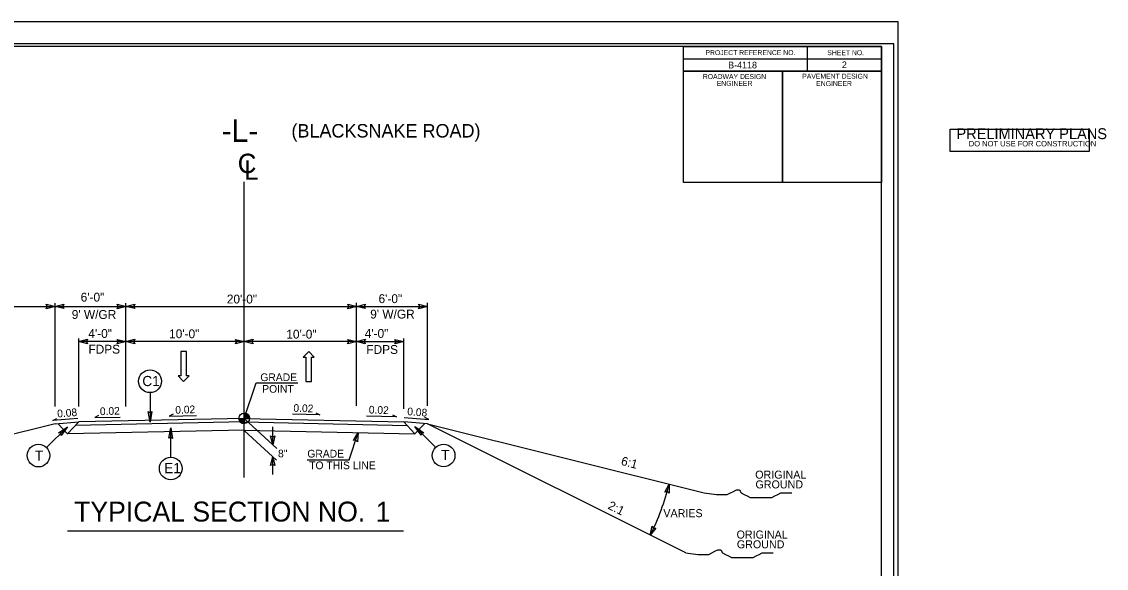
# Model space of a CAD drawing. Extents: x 573980 to 574178, y -53449 to -53334.
# Drawn here: x 574063.6 to 574178.2, y -53391.7 to -53334 of the extents above; entities that cross this region are included whole.
import ezdxf

# ---------------------------------------------------------------- set-up
doc = ezdxf.new("R2010")
doc.units = 0
for name, color, linetype in [('Old_Level_1', 7, 'Continuous'), ('Old_Level_11', 7, 'Continuous'), ('Old_Level_2', 7, 'Continuous'), ('Old_Level_3', 7, 'Continuous'), ('Prop Dimension Text', 7, 'Continuous'), ('Prop Lane Arrow CELL', 7, 'Continuous'), ('Sheet Data Field CELL', 7, 'Continuous'), ('Sheet Plot Border Inside CELL', 7, 'Continuous'), ('Sheet Plot Border Outside CELL', 7, 'Continuous'), ('Sheet Sticker Preliminary CELL', 7, 'Continuous'), ('Sheet Typical CELL', 7, 'Continuous'), ('Typical Berm CELL', 7, 'Continuous'), ('Typical Berm Information CELL', 7, 'Continuous'), ('Typical Grade Point Symbol CELL', 7, 'Continuous'), ('Typical ID Circle CELL', 7, 'Continuous'), ('Typical Pavement Slope CELL', 7, 'Continuous'), ('Typical Slope Point Local CELL', 7, 'Continuous'), ('Typical Terminator CELL', 7, 'Continuous'), ('Typical Text Centerline CELL', 7, 'Continuous'), ('Typical Text General CELL', 7, 'Continuous'), ('Typical Text Grade Point CELL', 7, 'Continuous'), ('Typical Text ID Circle CELL', 7, 'Continuous')]:
    doc.layers.add(name, color=color, linetype=linetype)

# ---------------------------------------------------------------- blocks, each defined once
blk = doc.blocks.new('TERMINATOR')
at = {"layer": 'Typical Terminator CELL'}
blk.add_lwpolyline([(-0.469, 0.081), (0, 0), (-0.471, -0.083), (-0.411, 0)], close=True, dxfattribs=at)
blk = doc.blocks.new('Lane Arrow Through')
at = {"layer": 'Prop Lane Arrow CELL'}
for p, q in [((-17.15, 1.6), (-3.15, 1.6)), ((-17.15, -1.7), (-17.15, 1.6)), ((-3.15, 1.6), (-3.15, 3.1)), ((-3.15, 3.1), (0, 0)), ((0, 0), (-3.15, -3.2)), ((-3.15, -1.7), (-17.15, -1.7)), ((-3.15, -3.2), (-3.15, -1.7))]:
    blk.add_line(p, q, dxfattribs=at)

msp = doc.modelspace()

# ---------------------------------------------------------------- linework, layer by layer
at = {"layer": 'Old_Level_1'}
msp.add_line((574068.4, -53387.77), (574103.91, -53387.77), dxfattribs=at)
at = {"layer": 'Old_Level_2'}
msp.add_line((574087.08, -53382.15), (574087.08, -53350.9), dxfattribs=at)
at = {"layer": 'Prop Dimension Text'}
for p, q in [((574057.08, -53364.07), (574106.45, -53364.07)), ((574067.08, -53374.65), (574067.08, -53363.72)), ((574074.58, -53374.65), (574074.58, -53363.72)), ((574098.95, -53374.59), (574098.95, -53363.69)), ((574106.45, -53374.59), (574106.45, -53363.69)), ((574069.58, -53374.65), (574069.58, -53367.47)), ((574074.58, -53367.78), (574069.58, -53367.78)), ((574099.02, -53367.78), (574072.08, -53367.78)), ((574098.95, -53374.59), (574098.95, -53367.4)), ((574098.95, -53367.78), (574103.95, -53367.78)), ((574103.95, -53374.88), (574103.95, -53367.47)), ((574087.14, -53375.97), (574090.52, -53379.08)), ((574090.09, -53378.69), (574090.09, -53376.79)), ((574087.12, -53377.21), (574090.49, -53380.33)), ((574090.09, -53381.83), (574090.09, -53379.96))]:
    msp.add_line(p, q, dxfattribs=at)
msp.add_arc((574106.45, -53376.46), 26.34, 333.4341, 345.9638, dxfattribs=at)
at = {"layer": 'Sheet Plot Border Inside CELL'}
msp.add_lwpolyline([(574155.75, -53336.33), (573981.44, -53336.33), (573981.44, -53446.69), (574155.75, -53446.69)], close=True, dxfattribs=at)
at = {"layer": 'Sheet Plot Border Outside CELL'}
msp.add_lwpolyline([(574156.22, -53333.98), (573980.08, -53333.98), (573980.08, -53449.04), (574156.22, -53449.04)], close=True, dxfattribs=at)
at = {"layer": 'Sheet Sticker Preliminary CELL'}
msp.add_lwpolyline([(574161.72, -53347.7), (574161.72, -53345.35), (574176.42, -53345.35), (574176.42, -53347.7)], close=True, dxfattribs=at)
at = {"layer": 'Sheet Typical CELL'}
for p, q in [((574146.6, -53336.6), (574146.6, -53339.22)), ((574133.52, -53337.91), (574154.44, -53337.91)), ((574143.98, -53339.22), (574143.98, -53350.98))]:
    msp.add_line(p, q, dxfattribs=at)
for points in [[(574154.44, -53336.6), (573997.55, -53336.6), (573997.55, -53446.42), (574154.44, -53446.42)], [(574133.52, -53336.6), (574154.44, -53336.6), (574154.44, -53339.22), (574133.52, -53339.22)], [(574133.52, -53339.22), (574143.98, -53339.22), (574143.98, -53350.98), (574133.52, -53350.98)], [(574143.98, -53339.22), (574154.44, -53339.22), (574154.44, -53350.98), (574143.98, -53350.98)]]:
    msp.add_lwpolyline(points, close=True, dxfattribs=at)
at = {"layer": 'Typical Berm CELL'}
for p, q in [((574087.08, -53375.9), (574069.58, -53376.27)), ((574087.08, -53375.9), (574103.95, -53376.26)), ((574068.39, -53377.55), (574067.37, -53376.45)), ((574068.39, -53377.55), (574069.58, -53376.27)), ((574087.1, -53377.15), (574068.39, -53377.55)), ((574087.08, -53376.28), (574069.22, -53376.65)), ((574087.05, -53377.15), (574105.13, -53377.53)), ((574087.07, -53376.28), (574104.3, -53376.64)), ((574105.13, -53377.53), (574103.95, -53376.26)), ((574105.13, -53377.53), (574106.16, -53376.43))]:
    msp.add_line(p, q, dxfattribs=at)
at = {"layer": 'Typical Berm Information CELL'}
for p, q in [((574071.69, -53375.61), (574071.28, -53375.82)), ((574071.28, -53375.82), (574073.96, -53375.76)), ((574079.58, -53375.45), (574079.16, -53375.66)), ((574079.16, -53375.66), (574082.02, -53375.6)), ((574095.07, -53375.53), (574092.19, -53375.47)), ((574094.66, -53375.32), (574095.07, -53375.53)), ((574103.18, -53375.74), (574100.01, -53375.67)), ((574102.76, -53375.53), (574103.18, -53375.74))]:
    msp.add_line(p, q, dxfattribs=at)
at = {"layer": 'Typical Grade Point Symbol CELL'}
for p, q in [((574087.08, -53375.9), (574088.33, -53372.15)), ((574086.52, -53375.9), (574087.08, -53375.9)), ((574087.08, -53375.9), (574087.08, -53375.34)), ((574087.64, -53375.9), (574087.08, -53375.9)), ((574087.08, -53376.46), (574087.08, -53375.9)), ((574087.08, -53375.9), (574087.08, -53376.46)), ((574098.17, -53380.29), (574099.13, -53377.41))]:
    msp.add_line(p, q, dxfattribs=at)
for points in [[(574086.52, -53375.9), (574086.52, -53375.96)], [(574086.53, -53375.9), (574086.53, -53376.03)], [(574086.54, -53375.9), (574086.54, -53376.07)], [(574086.55, -53375.9), (574086.55, -53376.1)], [(574086.56, -53375.9), (574086.56, -53376.13)], [(574086.58, -53375.9), (574086.58, -53376.15)], [(574086.59, -53375.9), (574086.59, -53376.17)], [(574086.6, -53375.9), (574086.6, -53376.19)], [(574086.61, -53375.9), (574086.61, -53376.21)], [(574086.62, -53375.9), (574086.62, -53376.23)], [(574086.63, -53375.9), (574086.63, -53376.24)], [(574086.64, -53375.9), (574086.64, -53376.26)], [(574086.65, -53375.9), (574086.65, -53376.27)], [(574086.67, -53375.9), (574086.67, -53376.28)], [(574086.68, -53375.9), (574086.68, -53376.3)], [(574086.69, -53375.9), (574086.69, -53376.31)], [(574086.7, -53375.9), (574086.7, -53376.32)], [(574086.71, -53375.9), (574086.71, -53376.33)], [(574086.72, -53375.9), (574086.72, -53376.34)], [(574086.73, -53375.9), (574086.73, -53376.35)], [(574086.74, -53375.9), (574086.74, -53376.35)], [(574086.75, -53375.9), (574086.75, -53376.36)], [(574086.77, -53375.9), (574086.77, -53376.37)], [(574086.78, -53375.9), (574086.78, -53376.38)], [(574086.79, -53375.9), (574086.79, -53376.38)], [(574086.8, -53375.9), (574086.8, -53376.39)], [(574086.81, -53375.9), (574086.81, -53376.4)], [(574086.82, -53375.9), (574086.82, -53376.4)], [(574086.83, -53375.9), (574086.83, -53376.41)], [(574086.84, -53375.9), (574086.84, -53376.41)], [(574086.86, -53375.9), (574086.86, -53376.42)], [(574086.87, -53375.9), (574086.87, -53376.42)], [(574086.88, -53375.9), (574086.88, -53376.43)], [(574086.89, -53375.9), (574086.89, -53376.43)], [(574086.9, -53375.9), (574086.9, -53376.43)], [(574086.91, -53375.9), (574086.91, -53376.44)], [(574086.92, -53375.9), (574086.92, -53376.44)], [(574086.93, -53375.9), (574086.93, -53376.44)], [(574086.95, -53375.9), (574086.95, -53376.45)], [(574086.96, -53375.9), (574086.96, -53376.45)], [(574086.97, -53375.9), (574086.97, -53376.45)], [(574086.98, -53375.9), (574086.98, -53376.45)], [(574086.99, -53375.9), (574086.99, -53376.46)], [(574087, -53375.9), (574087, -53376.46)], [(574087.01, -53375.9), (574087.01, -53376.46)], [(574087.02, -53375.9), (574087.02, -53376.46)], [(574087.03, -53375.9), (574087.03, -53376.46)], [(574087.05, -53375.9), (574087.05, -53376.46)], [(574087.06, -53375.9), (574087.06, -53376.46)], [(574087.07, -53375.9), (574087.07, -53376.46), (574087.07, -53376.46)], [(574087.08, -53375.34), (574087.08, -53375.34), (574087.08, -53375.9)], [(574087.09, -53375.34), (574087.09, -53375.9)], [(574087.1, -53375.35), (574087.1, -53375.9)], [(574087.12, -53375.35), (574087.12, -53375.9)], [(574087.13, -53375.35), (574087.13, -53375.9)], [(574087.14, -53375.35), (574087.14, -53375.9)], [(574087.15, -53375.35), (574087.15, -53375.9)], [(574087.16, -53375.35), (574087.16, -53375.9)], [(574087.17, -53375.35), (574087.17, -53375.9)], [(574087.18, -53375.35), (574087.18, -53375.9)], [(574087.19, -53375.36), (574087.19, -53375.9)], [(574087.2, -53375.36), (574087.2, -53375.9)], [(574087.22, -53375.36), (574087.22, -53375.9)], [(574087.23, -53375.37), (574087.23, -53375.9)], [(574087.24, -53375.37), (574087.24, -53375.9)], [(574087.25, -53375.37), (574087.25, -53375.9)], [(574087.26, -53375.38), (574087.26, -53375.9)], [(574087.27, -53375.38), (574087.27, -53375.9)], [(574087.28, -53375.38), (574087.28, -53375.9)], [(574087.29, -53375.39), (574087.29, -53375.9)], [(574087.31, -53375.39), (574087.31, -53375.9)], [(574087.32, -53375.4), (574087.32, -53375.9)], [(574087.33, -53375.4), (574087.33, -53375.9)], [(574087.34, -53375.41), (574087.34, -53375.9)], [(574087.35, -53375.42), (574087.35, -53375.9)], [(574087.36, -53375.42), (574087.36, -53375.9)], [(574087.37, -53375.43), (574087.37, -53375.9)], [(574087.38, -53375.44), (574087.38, -53375.9)], [(574087.4, -53375.44), (574087.4, -53375.9)], [(574087.41, -53375.45), (574087.41, -53375.9)], [(574087.42, -53375.46), (574087.42, -53375.9)], [(574087.43, -53375.47), (574087.43, -53375.9)], [(574087.44, -53375.48), (574087.44, -53375.9)], [(574087.45, -53375.49), (574087.45, -53375.9)], [(574087.46, -53375.5), (574087.46, -53375.9)], [(574087.47, -53375.51), (574087.47, -53375.9)], [(574087.48, -53375.52), (574087.48, -53375.9)], [(574087.5, -53375.53), (574087.5, -53375.9)], [(574087.51, -53375.55), (574087.51, -53375.9)], [(574087.52, -53375.56), (574087.52, -53375.9)], [(574087.53, -53375.58), (574087.53, -53375.9)], [(574087.54, -53375.59), (574087.54, -53375.9)], [(574087.55, -53375.61), (574087.55, -53375.9)], [(574087.56, -53375.63), (574087.56, -53375.9)], [(574087.57, -53375.65), (574087.57, -53375.9)], [(574087.59, -53375.67), (574087.59, -53375.9)], [(574087.6, -53375.7), (574087.6, -53375.9)], [(574087.61, -53375.73), (574087.61, -53375.9)], [(574087.62, -53375.77), (574087.62, -53375.9)], [(574087.63, -53375.82), (574087.63, -53375.9)]]:
    msp.add_lwpolyline(points, dxfattribs=at)
msp.add_circle((574087.08, -53375.9), 0.559, dxfattribs=at)
for start, end in [(179.9905, 269.9905), (359.9905, 89.9905)]:
    msp.add_arc((574087.08, -53375.9), 0.559, start, end, dxfattribs=at)
at = {"layer": 'Typical ID Circle CELL'}
for p, q in [((574077.12, -53373.18), (574077.12, -53376.29)), ((574066.18, -53378.98), (574068.38, -53376.79)), ((574079.31, -53380), (574079.31, -53376.89)), ((574107.32, -53378.97), (574105.12, -53376.77))]:
    msp.add_line(p, q, dxfattribs=at)
for centre in [(574077.12, -53371.98), (574065.33, -53379.83), (574108.16, -53379.82), (574079.31, -53381.2)]:
    msp.add_circle(centre, 1.2, dxfattribs=at)
at = {"layer": 'Typical Pavement Slope CELL'}
for p, q in [((574069.5, -53375.91), (574066.86, -53376.12)), ((574066.86, -53376.12), (574067.28, -53375.91)), ((574104, -53375.8), (574106.6, -53376.01)), ((574106.6, -53376.01), (574106.19, -53375.8))]:
    msp.add_line(p, q, dxfattribs=at)
at = {"layer": 'Typical Slope Point Local CELL'}
for p, q in [((574067.08, -53376.47), (574057.08, -53378.97)), ((574067.08, -53376.47), (574069.58, -53376.27)), ((574106.45, -53376.46), (574103.95, -53376.26)), ((574106.45, -53376.46), (574135.72, -53383.77)), ((574133.75, -53390.11), (574106.45, -53376.46))]:
    msp.add_line(p, q, dxfattribs=at)
for points in [[(574135.72, -53383.77), (574137.02, -53383.93), (574137.34, -53383.93), (574137.83, -53383.93), (574138.15, -53383.93), (574138.48, -53383.77), (574138.8, -53383.61), (574139.12, -53383.45), (574139.45, -53383.45), (574139.61, -53383.77), (574139.93, -53383.93), (574140.26, -53384.1), (574140.58, -53384.26), (574140.91, -53384.26), (574141.23, -53384.26), (574141.56, -53384.26), (574141.88, -53384.26), (574142.2, -53384.26), (574142.53, -53384.26), (574142.85, -53384.26), (574143.18, -53384.1), (574143.5, -53383.93), (574143.82, -53383.77), (574144.31, -53383.77), (574144.64, -53383.77), (574144.96, -53383.77)], [(574133.75, -53390.11), (574135.05, -53390.27), (574135.37, -53390.27), (574135.86, -53390.27), (574136.18, -53390.27), (574136.5, -53390.11), (574136.83, -53389.94), (574137.15, -53389.78), (574137.48, -53389.78), (574137.64, -53390.11), (574137.96, -53390.27), (574138.29, -53390.43), (574138.61, -53390.59), (574138.94, -53390.59), (574139.26, -53390.59), (574139.59, -53390.59), (574139.91, -53390.59), (574140.23, -53390.59), (574140.56, -53390.59), (574140.88, -53390.59), (574141.21, -53390.43), (574141.53, -53390.27), (574141.85, -53390.11), (574142.34, -53390.11), (574142.67, -53390.11), (574142.99, -53390.11)]]:
    msp.add_lwpolyline(points, dxfattribs=at)
at = {"layer": 'Typical Terminator CELL'}
for points in [[(574077.31, -53375.17), (574077.12, -53376.29), (574076.92, -53375.17), (574077.12, -53375.31)], [(574067.45, -53377.44), (574068.38, -53376.79), (574067.73, -53377.72), (574067.69, -53377.48)], [(574079.12, -53378), (574079.31, -53376.89), (574079.51, -53378.01), (574079.31, -53377.87)], [(574105.77, -53377.69), (574105.12, -53376.77), (574106.05, -53377.42), (574105.81, -53377.46)]]:
    msp.add_lwpolyline(points, close=True, dxfattribs=at)
at = {"layer": 'Typical Text Grade Point CELL'}
for p, q in [((574088.33, -53372.15), (574092.75, -53372.15)), ((574093.75, -53380.29), (574098.17, -53380.29))]:
    msp.add_line(p, q, dxfattribs=at)

# ---------------------------------------------------------------- block references
at = {"layer": 'Old_Level_1', "xscale": 0.18375, "yscale": -0.18375}
for p, rotation in [((574080.67, -53371.99), -89.99999999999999), ((574093.91, -53368.84), 90.00000000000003)]:
    msp.add_blockref('Lane Arrow Through', p, dxfattribs=dict(at, rotation=rotation))
at = {"layer": 'Old_Level_11', "xscale": 1.9883351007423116, "yscale": 2.853881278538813}
for p in [(574067.08, -53364.07), (574074.58, -53364.07), (574098.95, -53364.07), (574106.45, -53364.07), (574074.58, -53367.78), (574087.08, -53367.78), (574098.95, -53367.78), (574103.95, -53367.78)]:
    msp.add_blockref('TERMINATOR', p, dxfattribs=at)
at = {"layer": 'Old_Level_11'}
for p, xscale, yscale, rotation in [((574067.08, -53364.07), 1.9883351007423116, 2.853881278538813, 180), ((574074.58, -53364.07), 1.9883351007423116, 2.853881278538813, 180), ((574098.95, -53364.07), 1.9883351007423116, 2.853881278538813, 180), ((574069.58, -53367.78), 1.9883351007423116, 2.853881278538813, 180), ((574074.58, -53367.78), 1.9883351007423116, 2.853881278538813, 180), ((574087.08, -53367.78), 1.9883351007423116, 2.853881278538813, 180), ((574098.95, -53367.78), 1.9883351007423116, 2.853881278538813, 180), ((574090.09, -53378.69), 1.9883351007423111, 2.8538812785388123, -90.00000000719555), ((574099.13, -53377.41), 1.9883351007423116, 2.8538812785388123, 71.56505117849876), ((574090.09, -53379.96), 1.9883351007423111, 2.8538812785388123, 90.00000000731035), ((574132, -53382.84), 1.9883351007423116, 2.8538812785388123, 75.21793899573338), ((574130, -53388.23), 1.9883351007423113, 2.8538812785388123, -115.50066471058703)]:
    msp.add_blockref('TERMINATOR', p, dxfattribs=dict(at, xscale=xscale, yscale=yscale, rotation=rotation))

# ---------------------------------------------------------------- texts
at = {"layer": 'Old_Level_1'}
for s, p in [('ORIGINAL ', (574141.1, -53382.27)), ('GROUND', (574141.13, -53383.3)), ('VARIES', (574131.39, -53386.34)), ('ORIGINAL ', (574139.13, -53388.6)), ('GROUND', (574139.16, -53389.63))]:
    msp.add_text(s, height=0.846, dxfattribs=at).set_placement(p)
at = {"layer": 'Old_Level_11'}
msp.add_text('-L-', height=2.375, dxfattribs=at).set_placement((574084.68, -53346.68))
at = {"layer": 'Old_Level_3'}
for s, height, p in [('TYPICAL SECTION NO.  ', 2.1024, (574069.1, -53386.8)), ('1 ', 2.102, (574100.97, -53386.82))]:
    msp.add_text(s, height=height, dxfattribs=at).set_placement(p)
at = {"layer": 'Prop Dimension Text'}
for s, p in [('6\'-0"', (574069.79, -53363.56)), ('20\'-0"', (574085.24, -53363.76)), ('6\'-0"', (574101.28, -53363.72)), ("9' W/GR", (574068.85, -53365.39)), ("9' W/GR", (574100.4, -53365.35)), ('4\'-0"', (574070.6, -53367.4)), ('10\'-0"', (574079.14, -53367.43)), ('10\'-0"', (574091.53, -53367.47)), ('4\'-0"', (574099.82, -53367.39)), ('FDPS', (574070.61, -53369.06)), ('FDPS', (574099.99, -53369.09))]:
    msp.add_text(s, height=0.938, dxfattribs=at).set_placement(p)
msp.add_text('0.08 ', height=0.811, rotation=355.4261, dxfattribs=at).set_placement((574104.29, -53375.55))
at = {"layer": 'Sheet Data Field CELL'}
for s, p in [('2', (574150.26, -53338.89)), ('B-4118', (574138.24, -53338.92))]:
    msp.add_text(s, height=0.706, dxfattribs=at).set_placement(p)
at = {"layer": 'Sheet Sticker Preliminary CELL'}
for s, height, p in [('PRELIMINARY PLANS', 1.152, (574162.37, -53346.39)), ('DO NOT USE FOR CONSTRUCTION', 0.576, (574163.68, -53347.16))]:
    msp.add_text(s, height=height, dxfattribs=at).set_placement(p)
at = {"layer": 'Sheet Typical CELL'}
for s, p in [('PROJECT REFERENCE NO.', (574135.84, -53337.51)), ('SHEET NO.', (574148.72, -53337.52)), ('ROADWAY DESIGN', (574135.56, -53340.04)), ('ENGINEER', (574137.03, -53340.76)), ('PAVEMENT DESIGN', (574146.07, -53340)), ('ENGINEER', (574147.55, -53340.78))]:
    msp.add_text(s, height=0.523, dxfattribs=at).set_placement(p)
at = {"layer": 'Typical Berm CELL'}
msp.add_text('0.08', height=0.811, rotation=4.5739, dxfattribs=at).set_placement((574067.34, -53375.81))
at = {"layer": 'Typical Berm Information CELL'}
for rotation, p in [(1.8084, (574071.83, -53375.56)), (1.8084, (574079.8, -53375.41)), (358.1916, (574092.27, -53375.2)), (358.1916, (574100.24, -53375.38))]:
    msp.add_text('0.02', height=0.811, rotation=rotation, dxfattribs=at).set_placement(p)
at = {"layer": 'Typical Text Centerline CELL'}
msp.add_text('C', height=2.05, dxfattribs=at).set_placement((574086.39, -53349.98))
msp.add_text('L', height=2.05, rotation=359.9469, dxfattribs=at).set_placement((574087.08, -53350.68))
at = {"layer": 'Typical Text General CELL'}
msp.add_text('(BLACKSNAKE ROAD)', height=1.4233, dxfattribs=at).set_placement((574092.07, -53346.22))
for s, rotation, p in [('6:1', 345.1705, (574126.85, -53380.8)), ('2:1', 333.4349, (574125.44, -53385.41))]:
    msp.add_text(s, height=0.932, rotation=rotation, dxfattribs=at).set_placement(p)
at = {"layer": 'Typical Text Grade Point CELL'}
for s, height, p in [('GRADE', 0.816, (574088.78, -53371.96)), ('POINT', 0.816, (574088.98, -53373.19)), ('8"', 0.816, (574090.65, -53380.02)), ('GRADE', 0.816, (574093.75, -53380.04)), ('TO THIS LINE', 0.8156, (574093.95, -53381.27))]:
    msp.add_text(s, height=height, dxfattribs=at).set_placement(p)
at = {"layer": 'Typical Text ID Circle CELL'}
for s, height, p in [('C1', 1.076, (574076.31, -53372.49)), ('T', 1.08, (574064.95, -53380.38)), ('T', 1.08, (574107.9, -53380.31)), ('E1', 1.076, (574078.62, -53381.69))]:
    msp.add_text(s, height=height, dxfattribs=at).set_placement(p)

doc.saveas('drawing.dxf')
